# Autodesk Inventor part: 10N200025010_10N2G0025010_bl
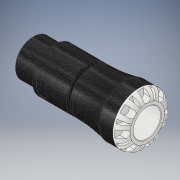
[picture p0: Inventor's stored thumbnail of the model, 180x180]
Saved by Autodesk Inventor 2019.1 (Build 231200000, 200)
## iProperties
Created: 2016-12
Part Number: 10N200025010_10N2G0025010_bl
Material: PVC-Piping
Description: PLASSON MALE ADAPTOR 25X1" SERIES 1
Document SubType Name: Modeling
Designer: KIM
Mass: 61.7504 g
Surface Area: 140.097 cm^2
Volume: 44.1074 cm^3
Density: 1.4 g/cm^3
Appearance: Black Cast
Author: KIM
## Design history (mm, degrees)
derived "10N20.ipt"
feature "Solid1::10N20.ipt" dims "ScaleForDerivedMember" = 10
tag "TaggingFeature1"
body "Solid1"
other parameters: "d0" = 104 [user parameter], "d1" = 20.16 [user parameter], "d2" = 25 [user parameter], "d3" = 31.25 [user parameter], "d4" = 47 [user parameter], "d6" = 48 [user parameter], "d8" = 39.95 [user parameter], "d13" = 6.3 [user parameter], "d14" = 6.3 [user parameter], "d15" = 0 [user parameter], "d17" = 360 deg [user parameter], "d19" = 8 deg [user parameter], "d20" = 0.5 [user parameter], "d21" = 0.5 [user parameter], "d22" = 8 deg [user parameter], "d24" = 0 [user parameter], "d26" = 360 deg [user parameter], "d32" = 0.925 [user parameter], "d33" = 4.7 [user parameter], "d34" = 33.249 [user parameter], "d35" = 2.08333 [user parameter], "d38" = 19 [user parameter], "d39" = 0.99747 [user parameter], "d42" = 8.75 [user parameter], "d43" = 5.75 [user parameter], "d45" = 12.348 [user parameter], "d46" = 0 [user parameter], "d59" = 360 deg [user parameter], "d61" = 7.4375 [user parameter], "d62" = 0.5 [user parameter], "d64" = 0 [user parameter], "d65" = 0.47 [user parameter], "d69" = 2 [user parameter], "d70" = 1.56 [user parameter], "d71" = 3 [user parameter], "d73" = 1 [user parameter], "d_" = 25 [user parameter], "E_" = 47 [user parameter], "H_" = 104 [user parameter], "l_" = 48 [user parameter], "R_" = 33.249 [user parameter], "l_2" = 19 [user parameter], "d9" = 7.875 [user parameter], "d11" = 47 [user parameter], "d12" = 31.25 [user parameter]
